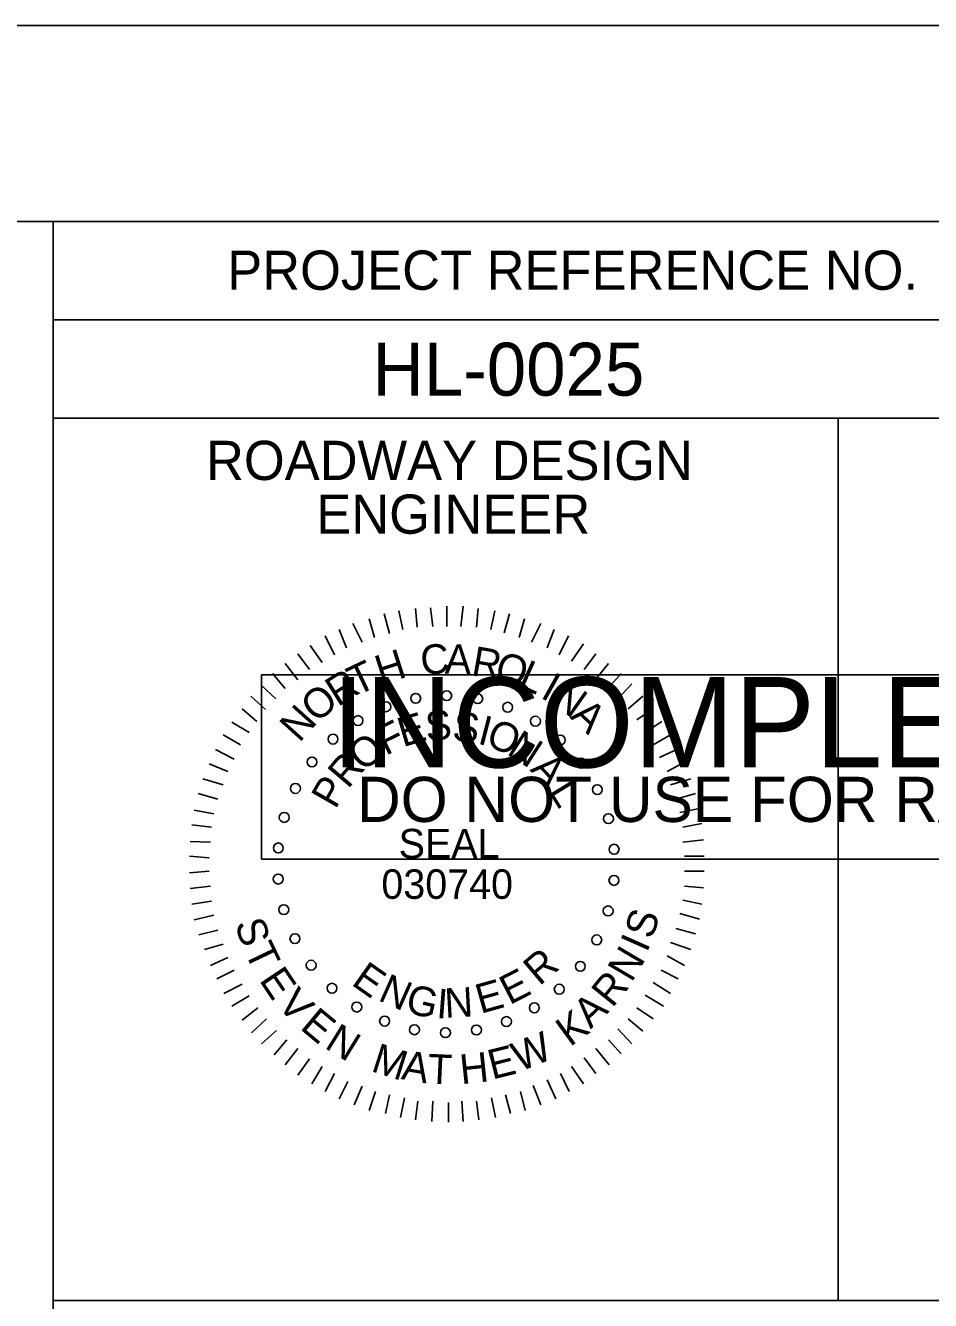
# Model space of a CAD drawing. Extents: x 1487909 to 1489267, y 497866 to 499814.
# Drawn here: x 1489029.61 to 1489041.14, y 498441.7 to 498457.95 of the extents above; entities that cross this region are included whole.
import ezdxf

# ---------------------------------------------------------------- set-up
doc = ezdxf.new("R2010")
doc.units = 0
for name, color, linetype in [('Old_Level_9', 7, 'Continuous'), ('Sheet Data Field CELL', 7, 'Continuous'), ('Sheet Plot Border Outside CELL', 7, 'Continuous'), ('Sheet Sticker Exception Certification CELL', 7, 'Continuous'), ('Sheet Sticker Incomplete CELL', 7, 'Continuous'), ('Sheet Typical CELL', 7, 'Continuous')]:
    doc.layers.add(name, color=color, linetype=linetype)

msp = doc.modelspace()

# ---------------------------------------------------------------- linework, layer by layer
at = {"layer": 'Old_Level_9'}
for p, q in [((1489034.368, 498450.49), (1489034.418, 498450.25)), ((1489034.578, 498450.52), (1489034.598, 498450.28)), ((1489034.768, 498450.53), (1489034.798, 498450.29)), ((1489034.978, 498450.55), (1489034.978, 498450.29)), ((1489035.188, 498450.55), (1489035.158, 498450.29)), ((1489035.378, 498450.52), (1489035.358, 498450.28)), ((1489035.588, 498450.49), (1489035.538, 498450.25)), ((1489033.778, 498450.33), (1489033.898, 498450.09)), ((1489033.988, 498450.39), (1489034.058, 498450.15)), ((1489034.178, 498450.45), (1489034.248, 498450.2)), ((1489035.778, 498450.45), (1489035.708, 498450.21)), ((1489035.968, 498450.39), (1489035.898, 498450.15)), ((1489036.178, 498450.33), (1489036.058, 498450.09)), ((1489033.428, 498450.17), (1489033.548, 498449.93)), ((1489033.608, 498450.25), (1489033.698, 498450.02)), ((1489036.348, 498450.25), (1489036.258, 498450.02)), ((1489036.528, 498450.17), (1489036.408, 498449.93)), ((1489033.238, 498450.05), (1489033.388, 498449.83)), ((1489036.718, 498450.07), (1489036.568, 498449.85)), ((1489032.918, 498449.82), (1489033.078, 498449.61)), ((1489033.078, 498449.94), (1489033.228, 498449.74)), ((1489036.878, 498449.94), (1489036.728, 498449.74)), ((1489037.038, 498449.82), (1489036.878, 498449.62)), ((1489032.758, 498449.69), (1489032.918, 498449.5)), ((1489037.198, 498449.69), (1489037.038, 498449.51)), ((1489032.618, 498449.54), (1489032.798, 498449.37)), ((1489037.338, 498449.56), (1489037.158, 498449.37)), ((1489032.478, 498449.4), (1489032.668, 498449.23)), ((1489037.478, 498449.4), (1489037.288, 498449.24)), ((1489032.368, 498449.24), (1489032.558, 498449.08)), ((1489037.608, 498449.24), (1489037.398, 498449.1)), ((1489032.238, 498449.07), (1489032.458, 498448.94)), ((1489037.718, 498449.08), (1489037.508, 498448.94)), ((1489032.128, 498448.91), (1489032.348, 498448.78)), ((1489037.828, 498448.91), (1489037.608, 498448.78)), ((1489032.028, 498448.72), (1489032.268, 498448.6)), ((1489037.928, 498448.73), (1489037.688, 498448.62)), ((1489031.948, 498448.54), (1489032.188, 498448.44)), ((1489038.008, 498448.56), (1489037.788, 498448.44)), ((1489031.868, 498448.35), (1489032.128, 498448.27)), ((1489038.088, 498448.35), (1489037.828, 498448.27)), ((1489031.808, 498448.16), (1489032.058, 498448.09)), ((1489038.148, 498448.16), (1489037.898, 498448.09)), ((1489031.758, 498447.95), (1489032.008, 498447.9)), ((1489038.198, 498447.97), (1489037.948, 498447.92)), ((1489031.728, 498447.76), (1489031.978, 498447.73)), ((1489038.228, 498447.78), (1489037.988, 498447.73)), ((1489031.708, 498447.55), (1489031.968, 498447.54)), ((1489038.248, 498447.57), (1489037.988, 498447.54)), ((1489031.698, 498447.36), (1489031.948, 498447.34)), ((1489038.258, 498447.36), (1489038.008, 498447.36)), ((1489031.698, 498447.15), (1489031.948, 498447.17)), ((1489038.258, 498447.17), (1489038.008, 498447.17)), ((1489031.708, 498446.95), (1489031.968, 498446.98)), ((1489038.248, 498446.96), (1489038.008, 498446.98)), ((1489031.728, 498446.75), (1489031.978, 498446.79)), ((1489038.228, 498446.75), (1489037.988, 498446.8)), ((1489031.758, 498446.55), (1489032.008, 498446.61)), ((1489038.198, 498446.56), (1489037.948, 498446.63)), ((1489031.818, 498446.36), (1489032.058, 498446.42)), ((1489038.148, 498446.37), (1489037.898, 498446.44)), ((1489031.888, 498446.17), (1489032.128, 498446.24)), ((1489038.088, 498446.17), (1489037.828, 498446.26)), ((1489031.968, 498445.97), (1489032.188, 498446.07)), ((1489038.008, 498445.97), (1489037.788, 498446.09)), ((1489032.048, 498445.8), (1489032.268, 498445.91)), ((1489037.928, 498445.8), (1489037.708, 498445.91)), ((1489037.828, 498445.61), (1489037.608, 498445.75)), ((1489032.138, 498445.61), (1489032.368, 498445.73)), ((1489032.238, 498445.45), (1489032.458, 498445.58)), ((1489037.738, 498445.45), (1489037.508, 498445.59)), ((1489032.368, 498445.27), (1489032.568, 498445.43)), ((1489037.608, 498445.29), (1489037.398, 498445.43)), ((1489032.488, 498445.11), (1489032.678, 498445.29)), ((1489037.478, 498445.13), (1489037.288, 498445.29)), ((1489032.618, 498444.97), (1489032.808, 498445.14)), ((1489037.338, 498444.97), (1489037.158, 498445.16)), ((1489032.778, 498444.83), (1489032.938, 498445.02)), ((1489037.198, 498444.84), (1489037.038, 498445.02)), ((1489032.918, 498444.7), (1489033.078, 498444.91)), ((1489033.078, 498444.57), (1489033.228, 498444.78)), ((1489036.878, 498444.59), (1489036.728, 498444.79)), ((1489037.048, 498444.7), (1489036.878, 498444.91)), ((1489033.258, 498444.46), (1489033.388, 498444.68)), ((1489036.718, 498444.46), (1489036.568, 498444.68)), ((1489033.428, 498444.36), (1489033.548, 498444.59)), ((1489033.608, 498444.27), (1489033.718, 498444.49)), ((1489036.368, 498444.27), (1489036.258, 498444.51)), ((1489036.538, 498444.36), (1489036.428, 498444.59)), ((1489033.798, 498444.19), (1489033.898, 498444.43)), ((1489033.988, 498444.12), (1489034.068, 498444.36)), ((1489034.198, 498444.08), (1489034.248, 498444.32)), ((1489034.388, 498444.03), (1489034.438, 498444.28)), ((1489035.598, 498444.03), (1489035.548, 498444.28)), ((1489035.788, 498444.08), (1489035.728, 498444.32)), ((1489035.978, 498444.12), (1489035.918, 498444.36)), ((1489036.178, 498444.19), (1489036.078, 498444.44)), ((1489034.578, 498444), (1489034.608, 498444.24)), ((1489034.788, 498443.98), (1489034.798, 498444.24)), ((1489034.998, 498443.97), (1489034.998, 498444.22)), ((1489035.188, 498443.98), (1489035.168, 498444.24)), ((1489035.388, 498444), (1489035.358, 498444.24))]:
    msp.add_line(p, q, dxfattribs=at)
for centre in [(1489034.201, 498449.267), (1489034.582, 498449.374), (1489034.977, 498449.409), (1489035.372, 498449.371), (1489035.753, 498449.261), (1489033.845, 498449.091), (1489036.108, 498449.083), (1489033.528, 498448.854), (1489036.423, 498448.842), (1489033.259, 498448.562), (1489036.689, 498448.548), (1489033.049, 498448.225), (1489036.896, 498448.21), (1489032.905, 498447.856), (1489037.038, 498447.84), (1489032.83, 498447.467), (1489037.11, 498447.45), (1489032.829, 498447.07), (1489037.108, 498447.053), (1489032.9, 498446.68), (1489037.034, 498446.664), (1489033.042, 498446.31), (1489036.889, 498446.295), (1489033.249, 498445.972), (1489036.679, 498445.958), (1489033.515, 498445.678), (1489036.411, 498445.666), (1489033.831, 498445.438), (1489036.093, 498445.429), (1489034.185, 498445.259), (1489035.738, 498445.253), (1489034.566, 498445.149), (1489034.961, 498445.111), (1489035.356, 498445.146)]:
    msp.add_circle(centre, 0.063, dxfattribs=at)
at = {"layer": 'Sheet Plot Border Outside CELL'}
msp.add_lwpolyline([(1489051.664, 498457.953), (1488883.264, 498457.953), (1488883.264, 498347.953), (1489051.664, 498347.953)], close=True, dxfattribs=at)
at = {"layer": 'Sheet Sticker Exception Certification CELL'}
for p, q in [((1489029.959, 498439.348), (1489029.959, 498441.698)), ((1489029.959, 498441.698), (1489049.962, 498441.698))]:
    msp.add_line(p, q, dxfattribs=at)
at = {"layer": 'Sheet Sticker Incomplete CELL'}
msp.add_lwpolyline([(1489032.614, 498447.323), (1489032.614, 498449.673), (1489047.314, 498449.673), (1489047.314, 498447.323)], close=True, dxfattribs=at)
at = {"layer": 'Sheet Typical CELL'}
for p, q in [((1489029.959, 498454.198), (1489049.964, 498454.198)), ((1489039.964, 498452.948), (1489039.964, 498441.703))]:
    msp.add_line(p, q, dxfattribs=at)
for points in [[(1489049.964, 498455.453), (1488899.964, 498455.453), (1488899.964, 498350.453), (1489049.964, 498350.453)], [(1489029.959, 498455.453), (1489049.964, 498455.453), (1489049.964, 498452.948), (1489029.959, 498452.948)], [(1489029.959, 498452.948), (1489039.964, 498452.948), (1489039.964, 498441.698), (1489029.959, 498441.698)], [(1489039.964, 498452.948), (1489049.964, 498452.948), (1489049.964, 498441.698), (1489039.964, 498441.698)]]:
    msp.add_lwpolyline(points, close=True, dxfattribs=at)

# ---------------------------------------------------------------- texts
at = {"layer": 'Old_Level_9'}
for s, height, rotation, p in [('H', 0.378, 17.7433, (1489034.138, 498449.54)), ('C', 0.378, 4.9399, (1489034.658, 498449.67)), ('A', 0.378, 357.9749, (1489034.948, 498449.69)), ('R', 0.378, 350.0216, (1489035.278, 498449.67)), ('T', 0.378, 25.4358, (1489033.828, 498449.4)), ('O', 0.378, 343.0868, (1489035.568, 498449.62)), ('L', 0.378, 335.7459, (1489035.868, 498449.53)), ('R', 0.378, 32.1754, (1489033.588, 498449.26)), ('I', 0.378, 330.806, (1489036.158, 498449.39)), ('O', 0.378, 39.9442, (1489033.318, 498449.05)), ('N', 0.378, 324.9038, (1489036.288, 498449.32)), ('N', 0.378, 48.0667, (1489033.098, 498448.8)), ('E', 0.376, 16.5889, (1489034.418, 498448.75)), ('S', 0.376, 4.468, (1489034.718, 498448.83)), ('S', 0.376, 353.0415, (1489035.038, 498448.84)), ('A', 0.378, 317.0051, (1489036.538, 498449.13)), ('F', 0.376, 26.4, (1489034.198, 498448.64)), ('I', 0.376, 345.4821, (1489035.358, 498448.8)), ('O', 0.376, 337.8749, (1489035.458, 498448.78)), ('O', 0.376, 38.2518, (1489033.908, 498448.43)), ('N', 0.376, 327.393, (1489035.728, 498448.67)), ('R', 0.376, 49.7478, (1489033.718, 498448.21)), ('A', 0.376, 313.9438, (1489036.028, 498448.46)), ('P', 0.376, 60.1236, (1489033.558, 498447.95)), ('L', 0.376, 301.5323, (1489036.268, 498448.19)), ('S', 0.378, 288.212, (1489032.273, 498446.502)), ('S', 0.378, 72.2579, (1489037.596, 498446.291)), ('T', 0.378, 295.6244, (1489032.392, 498446.15)), ('I', 0.378, 66.0464, (1489037.526, 498446.122)), ('R', 0.376, 40.3493, (1489036.158, 498445.7)), ('N', 0.378, 59.3726, (1489037.333, 498445.742)), ('E', 0.378, 303.8225, (1489032.579, 498445.782)), ('E', 0.376, 324.8692, (1489033.748, 498445.73)), ('E', 0.376, 27.1568, (1489035.778, 498445.46)), ('N', 0.376, 336.0584, (1489034.088, 498445.53)), ('E', 0.376, 15.8057, (1489035.408, 498445.35)), ('R', 0.378, 51.1503, (1489037.087, 498445.418)), ('V', 0.378, 311.9298, (1489032.805, 498445.464)), ('G', 0.376, 347.4812, (1489034.438, 498445.37)), ('I', 0.376, 355.6246, (1489034.838, 498445.3)), ('N', 0.376, 3.1278, (1489034.958, 498445.3)), ('E', 0.378, 320.2312, (1489033.094, 498445.167)), ('A', 0.378, 43.5217, (1489036.811, 498445.151)), ('K', 0.378, 36.141, (1489036.548, 498444.924)), ('N', 0.378, 328.329, (1489033.407, 498444.924)), ('W', 0.378, 22.0058, (1489035.903, 498444.608)), ('M', 0.378, 342.337, (1489033.998, 498444.624)), ('E', 0.378, 14.1648, (1489035.557, 498444.512)), ('A', 0.378, 350.1822, (1489034.387, 498444.521)), ('T', 0.378, 357.3866, (1489034.728, 498444.465)), ('H', 0.378, 6.0112, (1489035.163, 498444.454))]:
    msp.add_text(s, height=height, rotation=rotation, dxfattribs=at).set_placement(p)
for s, p in [('SEAL', (1489034.364, 498447.334)), ('030740', (1489034.144, 498446.818))]:
    msp.add_text(s, height=0.3759, dxfattribs=at).set_placement(p)
at = {"layer": 'Sheet Data Field CELL'}
msp.add_text('HL-0025', height=0.675, dxfattribs=at).set_placement((1489034.033, 498453.233))
at = {"layer": 'Sheet Sticker Incomplete CELL'}
for s, height, p in [('INCOMPLETE PLANS', 1.152, (1489033.509, 498448.493)), ('DO NOT USE FOR R/W ACQUISITION', 0.576, (1489033.834, 498447.798))]:
    msp.add_text(s, height=height, dxfattribs=at).set_placement(p)
at = {"layer": 'Sheet Typical CELL'}
for s, height, p in [('PROJECT REFERENCE NO.', 0.50001, (1489032.179, 498454.583)), ('ROADWAY DESIGN', 0.50001, (1489031.909, 498452.158)), ('ENGINEER', 0.5, (1489033.314, 498451.473))]:
    msp.add_text(s, height=height, dxfattribs=at).set_placement(p)

doc.saveas('drawing.dxf')
